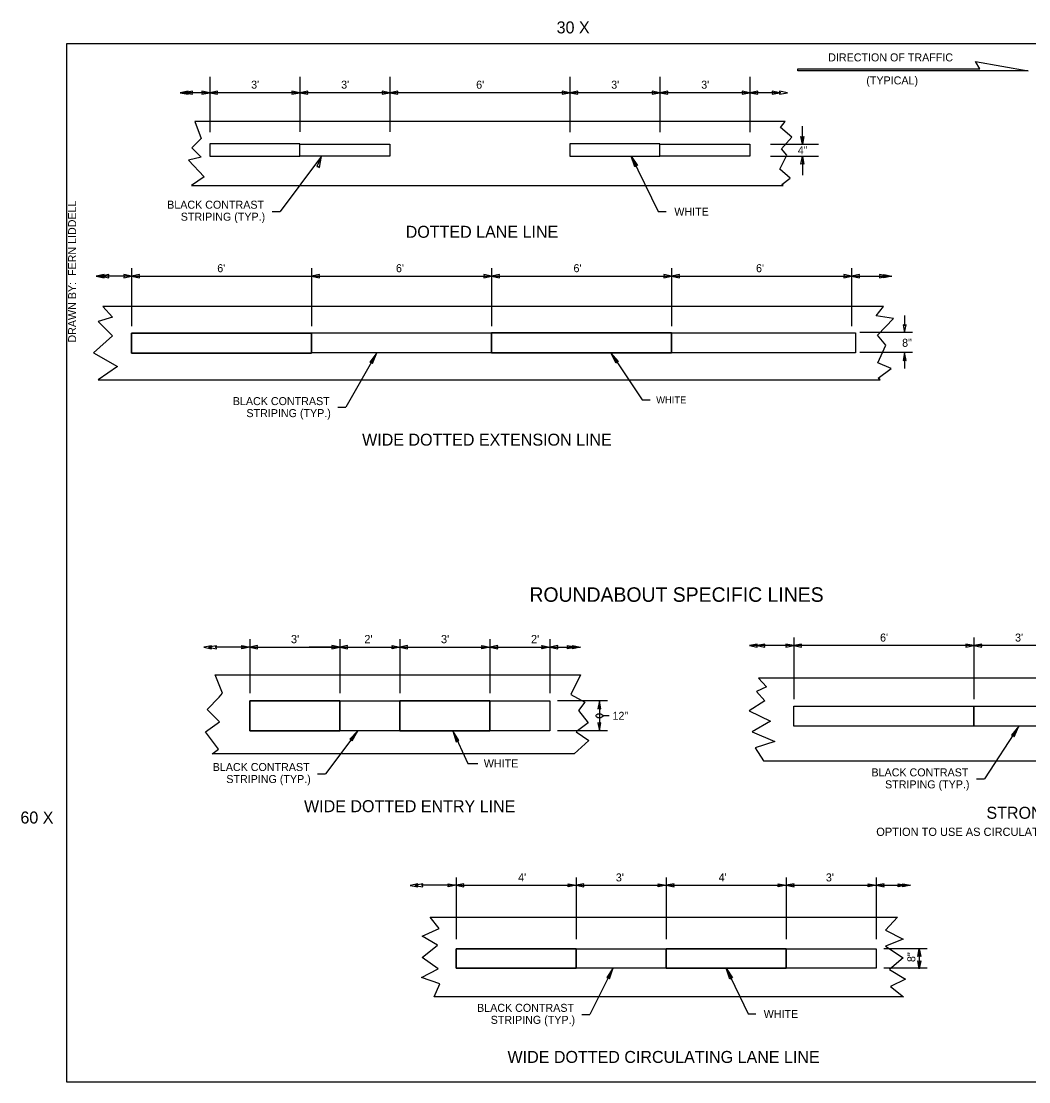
# Model space of a CAD drawing. Extents: x 99754 to 103681, y 99470 to 110996.
# Drawn here: x 99772 to 101787, y 108875 to 110996 of the extents above; entities that cross this region are included whole.
import ezdxf

# ---------------------------------------------------------------- set-up
doc = ezdxf.new("R2010")
doc.units = 0
for name, color, linetype in [('Level 1', 7, 'Continuous'), ('Level 10', 7, 'Continuous'), ('Level 12', 7, 'Continuous'), ('Level 15', 7, 'Continuous'), ('Level 18', 7, 'Continuous'), ('Level 2', 7, 'Continuous'), ('Level 20', 7, 'Continuous'), ('Level 6', 7, 'Continuous'), ('Level 60', 7, 'Continuous'), ('Level 62', 7, 'Continuous'), ('Level 7', 7, 'Continuous')]:
    doc.layers.add(name, color=color, linetype=linetype)

msp = doc.modelspace()

# ---------------------------------------------------------------- linework, layer by layer
at = {"layer": 'Level 1'}
msp.add_lwpolyline([(99863, 108875), (103152, 108875), (103152, 110951), (99863, 110951)], close=True, dxfattribs=at)
at = {"layer": 'Level 10'}
for p, q in [((99992.7, 110332), (99992.7, 110372)), ((99992.7, 110372), (100352.7, 110372)), ((100712.7, 110332.6), (100712.7, 110372.6)), ((100712.7, 110372.6), (101072.7, 110372.6)), ((100229.2, 109636.9), (100409.2, 109636.9)), ((100409.2, 109636.9), (100409.2, 109577)), ((100529.2, 109576.9), (100529.2, 109636.9)), ((100529.2, 109636.9), (100709.2, 109636.9)), ((100641.7, 109102.2), (100641.7, 109141.2)), ((100641.7, 109141.2), (100881.7, 109141.2)), ((100881.7, 109141.2), (100881.7, 109102.2)), ((101061.7, 109102.2), (101061.7, 109141.2)), ((101061.7, 109141.2), (101301.7, 109141.2)), ((101301.7, 109141.2), (101301.7, 109102.2)), ((100881.7, 109102.2), (100641.7, 109102.2)), ((101301.7, 109102.2), (101061.7, 109102.2))]:
    msp.add_line(p, q, dxfattribs=at)
for points in [[(100352.7, 110372), (100352.7, 110332)], [(101072.7, 110372.6), (101072.7, 110332.6)], [(100352.7, 110332), (99992.7, 110332)], [(101072.7, 110332.6), (100712.7, 110332.6)], [(100229.2, 109576.9), (100229.2, 109636.9)], [(100709.2, 109636.9), (100709.2, 109576.9)], [(100409.2, 109577), (100229.2, 109576.9)], [(100709.2, 109576.9), (100529.2, 109576.9)]]:
    msp.add_lwpolyline(points, dxfattribs=at)
at = {"layer": 'Level 12'}
for points in [[(100090.1, 110853.1), (100105.9, 110850), (100105.1, 110853.1), (100105.9, 110856.2)], [(100098.9, 110853.1), (100114.6, 110850), (100113.9, 110853.1), (100114.6, 110856.2)], [(100149.3, 110853.1), (100133.6, 110856.2), (100134.3, 110853.1), (100133.6, 110850)], [(100149.3, 110853.1), (100165, 110850), (100164.3, 110853.1), (100165, 110856.2)], [(100329.3, 110853.1), (100313.6, 110856.2), (100314.3, 110853.1), (100313.6, 110850)], [(100329.3, 110853.1), (100345, 110850), (100344.3, 110853.1), (100345, 110856.2)], [(100509.3, 110853.1), (100493.6, 110856.2), (100494.3, 110853.1), (100493.6, 110850)], [(100509.3, 110853.1), (100525, 110850), (100524.3, 110853.1), (100525, 110856.2)], [(100869.3, 110853.1), (100853.6, 110856.2), (100854.3, 110853.1), (100853.6, 110850)], [(100869.3, 110853.1), (100885, 110850), (100884.3, 110853.1), (100885, 110856.2)], [(101049.3, 110853.1), (101033.6, 110856.2), (101034.3, 110853.1), (101033.6, 110850)], [(101049.3, 110853.1), (101065, 110850), (101064.3, 110853.1), (101065, 110856.2)], [(101229.3, 110853.1), (101213.6, 110856.2), (101214.3, 110853.1), (101213.6, 110850)], [(101229.3, 110853.1), (101245, 110850), (101244.3, 110853.1), (101245, 110856.2)], [(101289.3, 110853.1), (101273.6, 110856.2), (101274.3, 110853.1), (101273.6, 110850)], [(101304.3, 110853.1), (101288.6, 110856.2), (101289.3, 110853.1), (101288.6, 110850)], [(101334.2, 110750.1), (101331.1, 110765.8), (101334.2, 110765.1), (101337.3, 110765.8)], [(101334.2, 110726.1), (101337.3, 110710.3), (101334.2, 110711.1), (101331.1, 110710.3)]]:
    msp.add_lwpolyline(points, close=True, dxfattribs=at)
at = {"layer": 'Level 15'}
for p, q in [((100149.3, 110885.1), (100149.3, 110774.1)), ((100329.3, 110885.1), (100329.3, 110774.6)), ((100509.3, 110885.1), (100509.3, 110774.6)), ((100869.3, 110885.1), (100869.3, 110774.1)), ((101049.3, 110885.1), (101049.3, 110774.1)), ((101229.3, 110885.1), (101229.3, 110774.1)), ((100149.3, 110853.1), (100090.1, 110853.1)), ((100329.3, 110853.1), (100149.3, 110853.1)), ((100509.3, 110853.1), (100329.3, 110853.1)), ((100869.3, 110853.1), (100509.3, 110853.1)), ((101049.3, 110853.1), (100869.3, 110853.1)), ((101229.3, 110853.1), (101049.3, 110853.1)), ((101291.3, 110853.1), (101229.3, 110853.1)), ((101334.2, 110750.1), (101334.2, 110786.2)), ((101270.3, 110750.1), (101366.2, 110750.1)), ((100372.7, 110726.3), (100289.7, 110615.8)), ((100991.9, 110726.3), (101046.1, 110615.8)), ((101270.3, 110726.1), (101366.2, 110726.1)), ((101334.2, 110726.1), (101334.2, 110688.5)), ((100273.7, 110615.8), (100289.7, 110615.8)), ((101046.1, 110615.8), (101062.1, 110615.8)), ((99992.7, 110502.1), (99992.7, 110386.2)), ((100352.7, 110502.1), (100352.7, 110386.2)), ((100712.7, 110502.1), (100712.7, 110386.2)), ((101072.7, 110502.1), (101072.7, 110386.2)), ((101432.7, 110502.1), (101432.7, 110386.2)), ((101432.7, 110502.1), (101432.7, 110386.2)), ((99992.8, 110486.1), (99922.2, 110486.1)), ((99992.7, 110486.1), (100352.7, 110486.1)), ((100352.7, 110486.1), (100712.7, 110486.1)), ((100712.7, 110486.1), (101072.7, 110486.1)), ((101072.7, 110486.1), (101432.7, 110486.1)), ((101433.8, 110486.1), (101513, 110486.1)), ((101538.5, 110407.7), (101538.5, 110387.1)), ((101554.5, 110373.2), (101449.3, 110373.2)), ((100951.4, 110332.6), (101013.8, 110238.7)), ((101554.5, 110333.2), (101449.3, 110333.2)), ((101538.5, 110333.2), (101538.5, 110301.4)), ((101013.8, 110238.7), (101029.8, 110238.7)), ((100405.2, 110224.5), (100421.2, 110224.5)), ((100229.2, 109744.3), (100160.3, 109744.3)), ((100229.2, 109760.3), (100229.2, 109651.9)), ((100229.2, 109744.3), (100409.2, 109744.3)), ((100409.2, 109744.3), (100348.2, 109744.3)), ((100409.2, 109760.3), (100409.2, 109651.9)), ((100409.2, 109744.3), (100529.2, 109744.3)), ((100529.2, 109760.3), (100529.2, 109651.9)), ((100529.2, 109744.3), (100709.2, 109744.3)), ((100709.2, 109760.3), (100709.2, 109651.9)), ((100709.2, 109744.3), (100829.2, 109744.3)), ((100829.2, 109760.3), (100829.2, 109651.9)), ((100829.2, 109744.3), (100890.2, 109744.3)), ((101676.9, 109747.4), (101228.2, 109747.4)), ((101316.9, 109763.4), (101316.9, 109640.3)), ((101676.9, 109763.4), (101676.9, 109640.3)), ((101856.9, 109747.4), (101676.9, 109747.4)), ((100944.2, 109636.9), (100844.2, 109636.9)), ((100947.9, 109606.9), (100935.4, 109606.9)), ((100445.5, 109576.9), (100380.7, 109491.2)), ((100635.1, 109576.9), (100664.9, 109511.6)), ((100944.2, 109576.9), (100844.2, 109576.9)), ((101766.9, 109586), (101698, 109480.6)), ((100664.9, 109511.6), (100685.2, 109511.6)), ((100364.8, 109491.2), (100380.7, 109491.2)), ((101682, 109480.6), (101698, 109480.6)), ((100641.7, 109283.7), (100641.7, 109159.9)), ((100881.7, 109283.7), (100881.7, 109159.9)), ((101061.7, 109283.7), (101061.7, 109159.9)), ((101061.7, 109283.7), (101061.7, 109159.9)), ((101301.7, 109283.7), (101301.7, 109159.9)), ((101481.7, 109283.7), (101481.7, 109159.9)), ((101481.7, 109283.7), (101481.7, 109159.9)), ((100641.7, 109268.1), (100572.8, 109268.1)), ((100641.7, 109268.1), (100881.7, 109268.1)), ((100881.7, 109268.1), (101061.7, 109268.1)), ((101061.7, 109268.1), (101301.7, 109268.1)), ((101301.7, 109268.1), (101481.7, 109268.1)), ((101481.7, 109268.1), (101550.6, 109268.1)), ((101584, 109141.2), (101497.1, 109141.2)), ((101568, 109141.2), (101568, 109101.2)), ((100956, 109102.9), (100909.4, 109009.7)), ((101181.7, 109102.2), (101225.5, 109010.6)), ((101584, 109102.2), (101497.1, 109102.2)), ((100893.4, 109009.7), (100909.4, 109009.7)), ((101225.5, 109010.6), (101240.8, 109010.6))]:
    msp.add_line(p, q, dxfattribs=at)
for points in [[(99922.2, 110486.1), (99937.9, 110483), (99937.2, 110486.1), (99937.9, 110489.2)], [(99931.8, 110486.1), (99947.6, 110483), (99946.8, 110486.1), (99947.6, 110489.2)], [(99992.8, 110486.1), (99977.1, 110489.2), (99977.8, 110486.1), (99977.1, 110483)], [(101513, 110486.1), (101497.3, 110483), (101498, 110486.1), (101497.3, 110489.2)], [(100137.1, 109743.9), (100152.8, 109740.8), (100152.1, 109743.9), (100152.8, 109747)], [(100146.8, 109743.9), (100162.5, 109740.8), (100161.8, 109743.9), (100162.5, 109747)], [(100409.2, 109744.3), (100393.4, 109747.4), (100394.2, 109744.3), (100393.4, 109741.2)], [(100880.5, 109744.3), (100864.8, 109741.2), (100865.5, 109744.3), (100864.8, 109747.4)], [(100890.2, 109744.3), (100874.4, 109741.2), (100875.2, 109744.3), (100874.4, 109747.4)], [(100549.6, 109267.7), (100565.4, 109264.6), (100564.6, 109267.7), (100565.4, 109270.8)], [(100559.3, 109267.7), (100575, 109264.6), (100574.3, 109267.7), (100575, 109270.8)], [(101541.2, 109268.1), (101525.9, 109265.1), (101526.6, 109268.1), (101525.9, 109271.1)], [(101550.6, 109268.1), (101535.3, 109265.1), (101536, 109268.1), (101535.3, 109271.1)]]:
    msp.add_lwpolyline(points, close=True, dxfattribs=at)
msp.add_ellipse((100928.2, 109606.9), major_axis=(-7.2, 0), ratio=0.57735, dxfattribs=at)
at = {"layer": 'Level 18'}
for p, q in [((100352.7, 110372), (99992.7, 110372)), ((101072.7, 110372.6), (100712.7, 110372.6)), ((100409.2, 109636.9), (100229.2, 109636.9)), ((100709.2, 109636.9), (100529.2, 109636.9))]:
    msp.add_line(p, q, dxfattribs=at)
at = {"layer": 'Level 2'}
for points in [[(100509.3, 110750.3), (100509.3, 110726.3), (100329.3, 110726.3), (100329.3, 110750.3), (100509.3, 110750.3)], [(101229.3, 110750.3), (101229.3, 110726.3), (101049.3, 110726.3), (101049.3, 110750.3), (101229.3, 110750.3)], [(100712.7, 110372.6), (100712.7, 110332.6), (100352.7, 110332.6), (100352.7, 110372.6), (100712.7, 110372.6)], [(101440.4, 110372.6), (101440.4, 110332.6), (101072.7, 110332.6), (101072.7, 110372.6), (101440.4, 110372.6)], [(100529.2, 109636.9), (100529.2, 109576.9), (100409.1, 109576.9), (100409.2, 109636.9), (100529.2, 109636.9)], [(100829.2, 109636.9), (100829.2, 109576.9), (100709.1, 109576.9), (100709.2, 109636.9), (100829.2, 109636.9)], [(101856.9, 109626), (101856.9, 109586), (101676.9, 109586), (101676.9, 109626), (101856.9, 109626)], [(101061.7, 109141.2), (101061.7, 109102.2), (100881.7, 109102.2), (100881.7, 109141.2), (101061.7, 109141.2)], [(101481.7, 109141.2), (101481.7, 109102.2), (101301.7, 109102.2), (101301.7, 109141.2), (101481.7, 109141.2)]]:
    msp.add_lwpolyline(points, dxfattribs=at)
at = {"layer": 'Level 20'}
for p, q in [((100483.2, 110332.6), (100421.2, 110224.5)), ((101526, 110333.6), (101526, 110333.5)), ((100928.2, 109636.9), (100928.2, 109576.9))]:
    msp.add_line(p, q, dxfattribs=at)
for points in [[(101324.8, 110900.8), (101689.1, 110900.8), (101680.6, 110915.6), (101785.5, 110897.1), (101324.8, 110897.1)], [(100372.7, 110726.3), (100363.1, 110705.4), (100366.2, 110705.6), (100368.8, 110703.7)], [(100991.9, 110726.3), (101004.7, 110707.3), (101001.6, 110706.9), (100999.4, 110704.6)], [(99992.8, 110486.1), (100008.5, 110483), (100007.8, 110486.1), (100008.5, 110489.2)], [(100352.8, 110486.1), (100368.5, 110483), (100367.8, 110486.1), (100368.5, 110489.2)], [(100712.8, 110486.1), (100697.1, 110489.2), (100697.9, 110486.1), (100697.1, 110483)], [(100712.7, 110486.1), (100728.4, 110483), (100727.7, 110486.1), (100728.4, 110489.2)], [(101072.7, 110486.1), (101057, 110489.2), (101057.7, 110486.1), (101057, 110483)], [(101072.7, 110486.1), (101088.4, 110483), (101087.7, 110486.1), (101088.4, 110489.2)], [(101432.7, 110486.1), (101417, 110489.2), (101417.7, 110486.1), (101417, 110483)], [(101432.7, 110486.1), (101448.4, 110483), (101447.7, 110486.1), (101448.4, 110489.2)], [(101503.8, 110486.1), (101488.1, 110489.2), (101488.9, 110486.1), (101488.1, 110483)], [(101538.5, 110373.2), (101541.6, 110389), (101538.5, 110388.2), (101535.4, 110389)], [(100483.2, 110332.6), (100469.3, 110314.3), (100472.4, 110313.7), (100474.5, 110311.3)], [(100951.4, 110332.6), (100966.7, 110315.4), (100963.6, 110314.6), (100961.7, 110312.1)], [(101538.5, 110333.2), (101535.4, 110317.5), (101538.5, 110318.2), (101541.6, 110317.5)], [(100229.2, 109744.3), (100213.5, 109741.2), (100214.2, 109744.3), (100213.5, 109747.4)], [(100229.2, 109744.3), (100244.9, 109741.2), (100244.2, 109744.3), (100244.9, 109747.4)], [(100409.2, 109744.3), (100424.9, 109741.2), (100424.2, 109744.3), (100424.9, 109747.4)], [(100529.4, 109744.3), (100513.7, 109741.2), (100514.4, 109744.3), (100513.7, 109747.4)], [(100529.2, 109744.3), (100544.9, 109741.2), (100544.2, 109744.3), (100544.9, 109747.4)], [(100709.2, 109744.3), (100693.4, 109741.2), (100694.2, 109744.3), (100693.4, 109747.4)], [(100709.2, 109744.3), (100693.4, 109741.2), (100694.2, 109744.3), (100693.4, 109747.4)], [(100709.2, 109744.3), (100724.9, 109741.2), (100724.2, 109744.3), (100724.9, 109747.4)], [(100829.2, 109744.3), (100813.4, 109741.2), (100814.2, 109744.3), (100813.4, 109747.4)], [(100829.2, 109744.3), (100844.9, 109741.2), (100844.2, 109744.3), (100844.9, 109747.4)], [(101228.2, 109747.4), (101244, 109744.3), (101243.2, 109747.4), (101244, 109750.5)], [(101243.2, 109747.4), (101259, 109744.3), (101258.2, 109747.4), (101259, 109750.5)], [(101316.9, 109747.4), (101301.2, 109750.5), (101301.9, 109747.4), (101301.2, 109744.3)], [(101316.9, 109747.4), (101332.7, 109744.3), (101331.9, 109747.4), (101332.7, 109750.5)], [(101676.9, 109747.4), (101661.2, 109750.5), (101661.9, 109747.4), (101661.2, 109744.3)], [(101676.9, 109747.4), (101692.7, 109744.3), (101691.9, 109747.4), (101692.7, 109750.5)], [(100928.2, 109636.9), (100925.1, 109621.2), (100928.2, 109621.9), (100931.3, 109621.2)], [(100445.5, 109576.9), (100429.3, 109560.5), (100432.4, 109559.6), (100434.1, 109556.9)], [(100635.1, 109576.9), (100642, 109555), (100644.3, 109557.2), (100647.4, 109557.5)], [(100928.2, 109576.9), (100931.3, 109592.7), (100928.2, 109591.9), (100925.1, 109592.7)], [(101766.9, 109586), (101752.6, 109568), (101755.7, 109567.3), (101757.7, 109564.9)], [(100641.7, 109268.1), (100626, 109265), (100626.7, 109268.1), (100626, 109271.2)], [(100641.7, 109268.1), (100657.5, 109265), (100656.7, 109268.1), (100657.5, 109271.2)], [(100881.7, 109268.1), (100866, 109265), (100866.7, 109268.1), (100866, 109271.2)], [(100881.7, 109268.1), (100897.5, 109265), (100896.7, 109268.1), (100897.5, 109271.2)], [(101061.7, 109268.1), (101046, 109265), (101046.7, 109268.1), (101046, 109271.2)], [(101061.7, 109268.1), (101077.5, 109265), (101076.7, 109268.1), (101077.5, 109271.2)], [(101301.7, 109268.1), (101286, 109265), (101286.7, 109268.1), (101286, 109271.2)], [(101301.7, 109268.1), (101317.5, 109265), (101316.7, 109268.1), (101317.5, 109271.2)], [(101481.7, 109268.1), (101466, 109265), (101466.7, 109268.1), (101466, 109271.2)], [(101481.7, 109268.1), (101497.5, 109265), (101496.7, 109268.1), (101497.5, 109271.2)], [(101568, 109141.2), (101571.1, 109125.5), (101568, 109126.2), (101564.9, 109125.5)], [(101568, 109101.2), (101564.9, 109116.9), (101568, 109116.2), (101571.1, 109116.9)], [(100956.1, 109102.9), (100943.1, 109083.9), (100946.3, 109083.5), (100948.4, 109081.2)], [(101181.7, 109102.2), (101194.3, 109082.9), (101191.1, 109082.6), (101188.9, 109080.3)]]:
    msp.add_lwpolyline(points, close=True, dxfattribs=at)
at = {"layer": 'Level 6'}
for points in [[(100329.3, 110750.6), (100149.3, 110750.6), (100149.3, 110726.3), (100329.3, 110726.3)], [(101049.3, 110750.6), (100869.3, 110750.6), (100869.3, 110726.3), (101049.3, 110726.3)], [(100352.7, 110372), (99992.7, 110372), (99992.7, 110332), (100352.7, 110332)], [(101072.7, 110372.6), (100712.7, 110372.6), (100712.7, 110332.6), (101072.7, 110332.6)], [(100409.2, 109636.9), (100229.2, 109636.9), (100229.2, 109576.9), (100409.2, 109577)], [(100709.2, 109636.9), (100529.2, 109636.9), (100529.2, 109576.9), (100709.2, 109576.9)], [(100881.7, 109141.2), (100641.7, 109141.2), (100641.7, 109102.2), (100881.7, 109102.2)], [(101301.7, 109141.2), (101061.7, 109141.2), (101061.7, 109102.2), (101301.7, 109102.2)]]:
    msp.add_lwpolyline(points, close=True, dxfattribs=at)
msp.add_lwpolyline([(101676.9, 109626), (101676.9, 109586), (101316.9, 109586), (101316.9, 109626), (101676.9, 109626)], dxfattribs=at)
at = {"layer": 'Level 60'}
msp.add_line((99863, 108875), (99863, 108875), dxfattribs=at)
at = {"layer": 'Level 7'}
for p, q in [((101299.8, 110795.5), (100119.3, 110795.5)), ((100112.9, 110667.4), (101295.6, 110667.4)), ((101496.5, 110425.5), (99935.6, 110425.5)), ((100159.7, 109689), (100890.5, 109689)), ((102456.2, 109682.3), (101246.5, 109682.3)), ((100877.6, 109531), (100153.9, 109531)), ((101256.7, 109517.2), (102454.8, 109517.2)), ((100590.2, 109204.1), (101524.2, 109204.1)), ((101536.2, 109045.2), (100598.1, 109045.2))]:
    msp.add_line(p, q, dxfattribs=at)
for points in [[(100119.3, 110795.5), (100131.8, 110761.7), (100113.2, 110742.7), (100131.8, 110724), (100106.7, 110718), (100138.3, 110684.8), (100112.9, 110667.4)], [(101295.6, 110667.4), (101292.9, 110669.8), (101309.8, 110682.4), (101288.8, 110700.4), (101302.9, 110727.9), (101292.1, 110740.9), (101312.8, 110764), (101290.3, 110783.4), (101299.8, 110795.5)], [(99935.6, 110425.5), (99954.8, 110404.4), (99926.3, 110395.3), (99954.8, 110366.8), (99916.4, 110333.1), (99964.7, 110305.4), (99925.8, 110278.8)], [(101490, 110278.8), (101485.9, 110282.4), (101511.7, 110301.6), (101485.2, 110312.8), (101501.1, 110348.3), (101484.6, 110368.1), (101516.3, 110401.2), (101481.9, 110407), (101496.5, 110425.5)], [(99925.8, 110278.8), (101490, 110278.8)], [(100153.9, 109531), (100161.1, 109536.5), (100167, 109540.4), (100140.7, 109574.9), (100168.4, 109595.2), (100143.9, 109619.5), (100167.7, 109643.9), (100174.6, 109652), (100159.7, 109689)], [(100890.5, 109689), (100870.9, 109649.3), (100899, 109634.2), (100886.3, 109617.8), (100906, 109593), (100881.7, 109574.9), (100907.1, 109557.3), (100877.6, 109531)], [(101246.5, 109682.3), (101262.2, 109665), (101242.7, 109655.4), (101259, 109636.8), (101227.7, 109617.2), (101270.2, 109596.2), (101233.5, 109574.6), (101279.4, 109555.3), (101240, 109542.6), (101256.7, 109517.2)], [(100598.1, 109045.2), (100609, 109071), (100572.4, 109083.3), (100605.6, 109100.8), (100573.8, 109123.7), (100604.8, 109148), (100574, 109166.4), (100608.1, 109181.4), (100590.2, 109204.1)], [(101524.2, 109204.1), (101500.6, 109178.1), (101535.5, 109160.4), (101500.6, 109146.4), (101535.7, 109122.8), (101508.3, 109099.3), (101540.4, 109080.4), (101510.4, 109065.8), (101536.2, 109045.2)]]:
    msp.add_lwpolyline(points, dxfattribs=at)

# ---------------------------------------------------------------- texts
at = {"layer": 'Level 15'}
for s, p in [('30 X', (100842.8, 110971.7)), ('60 X', (99770.6, 109391.5))]:
    msp.add_text(s, height=24, dxfattribs=at).set_placement(p)
at = {"layer": 'Level 20'}
for s, height, p in [('DIRECTION OF TRAFFIC', 16, (101385.8, 110915.7)), ("3'", 16, (100231.9, 110861.2)), ("3'", 16, (100411.9, 110861.2)), ("6'", 16, (100681.9, 110861.1)), ("3'", 16, (100951.9, 110861.1)), ("3'", 16, (101131.9, 110861.1)), ('(TYPICAL)', 16, (101462, 110869.7)), ('BLACK CONTRAST ', 16, (100064, 110621.1)), ('STRIPING (TYP.)', 16, (100091.2, 110597.1)), ('WHITE', 16, (101078.1, 110607.2)), ('DOTTED LANE LINE', 24, (100541, 110562.9)), ('BLACK CONTRAST ', 16, (100195.3, 110228.3)), ('WHITE', 14, (101041.8, 110231.7)), ('STRIPING (TYP.)', 16, (100222.5, 110204.3)), ('WIDE DOTTED EXTENSION LINE', 24, (100453.8, 110147.2)), ('ROUNDABOUT SPECIFIC LINES', 29, (100788.4, 109834.9)), ("6'", 16, (101489.5, 109755.4)), ("3'", 16, (101759.5, 109755.4)), ('BLACK CONTRAST ', 16, (100155.1, 109496.5)), ('WHITE', 16, (100697.2, 109503.6)), ('BLACK CONTRAST ', 16, (101472.3, 109485.8)), ('STRIPING (TYP.)', 16, (100182.3, 109472.5)), ('STRIPING (TYP.)', 16, (101499.5, 109461.8)), ('WIDE DOTTED ENTRY LINE', 24, (100337.7, 109414.2)), ('STRONG LANE LINE', 24, (101702.2, 109401)), ('OPTION TO USE AS CIRCULATORY ON ROUNDABOUT APPLICATIONS', 16.5, (101481.9, 109366.7)), ('BLACK CONTRAST ', 16, (100683.7, 109014.9)), ('STRIPING (TYP.)', 16, (100710.9, 108990.9)), ('WHITE', 16, (101256.8, 109002.6)), ('WIDE DOTTED CIRCULATING LANE LINE', 24, (100744.6, 108912.7))]:
    msp.add_text(s, height=height, dxfattribs=at).set_placement(p)
for s, height, rotation, p in [('4"', 16, 360, (101325, 110730)), ("6' ", 16, 360, (100164.2, 110494.1)), ("6' ", 16, 360, (100521.5, 110494.1)), ("6' ", 16, 360, (100876.5, 110494.1)), ("6' ", 16, 360, (101241.5, 110494.1)), ('8"', 16, 360, (101533.6, 110344.9)), ("3' ", 16.5, 360, (100311.5, 109752.1)), ("2' ", 16.5, 360, (100458.3, 109752.1)), ("3' ", 16.5, 360, (100611.5, 109752.1)), ("2' ", 16.5, 360, (100791.5, 109752.1)), ('12"', 16, 360, (100954.5, 109598.9)), ("4' ", 16, 360, (100765.8, 109275.7)), ("3' ", 16, 360, (100961.2, 109275.7)), ("4' ", 16, 360, (101166.7, 109275.7)), ("3' ", 16, 360, (101381.2, 109275.7)), ('8"', 16, 90, (101560, 109114.5))]:
    msp.add_text(s, height=height, rotation=rotation, dxfattribs=at).set_placement(p)
at = {"layer": 'Level 62'}
msp.add_text('DRAWN BY:  FERN LIDDELL', height=16, rotation=90, dxfattribs=at).set_placement((99882, 110353.3))

doc.saveas('drawing.dxf')
